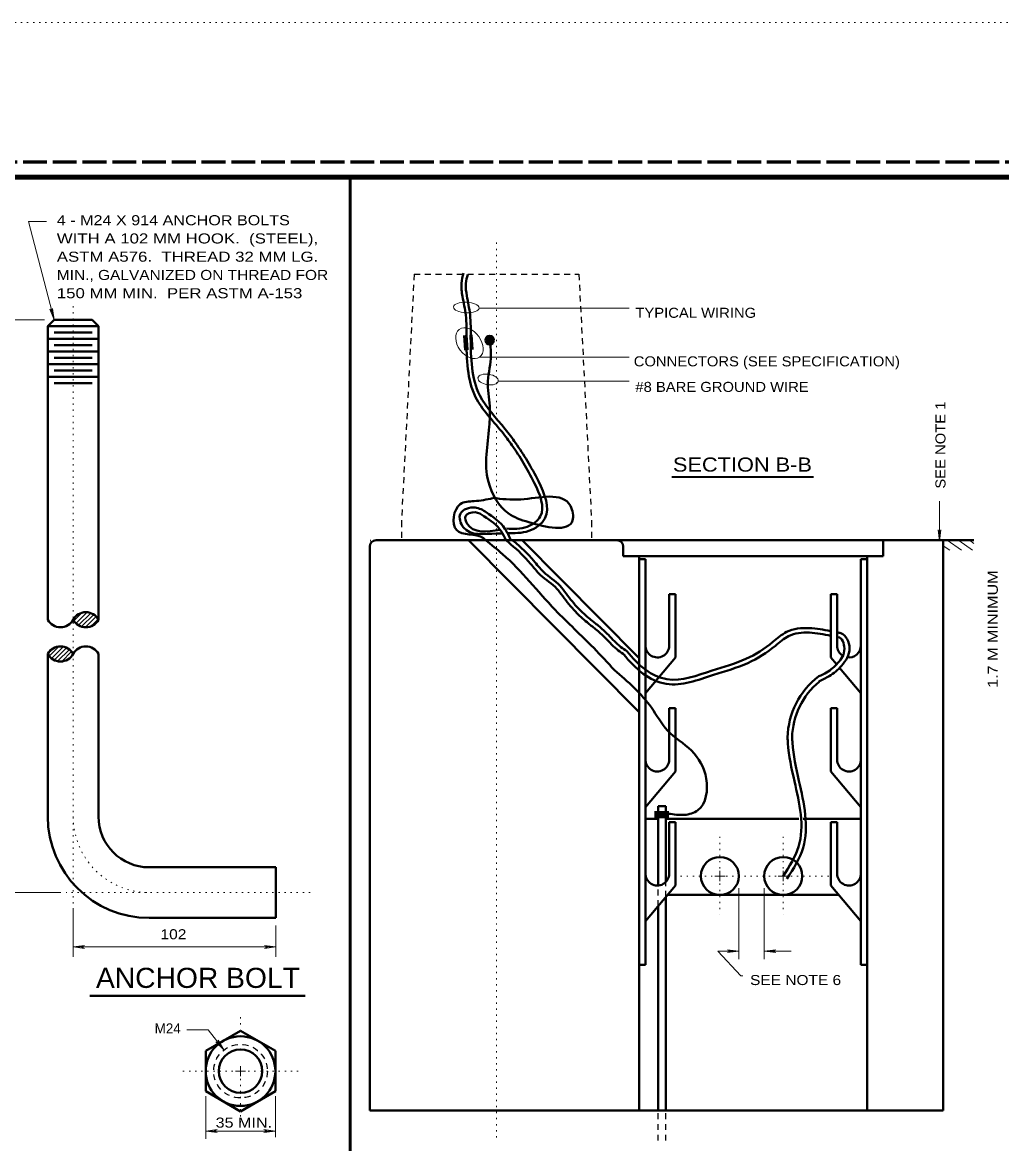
# Model space of a CAD drawing. Extents: x 312583 to 312854, y 144419 to 144597.
# Drawn here: x 312692.4 to 312766.4, y 144512 to 144596.8 of the extents above; entities that cross this region are included whole.
import ezdxf
from ezdxf.enums import TextEntityAlignment as Align

# ---------------------------------------------------------------- set-up
doc = ezdxf.new("R2010")
doc.units = 0
doc.header["$LTSCALE"] = 0.3
doc.header["$PDMODE"] = 32
doc.header["$PDSIZE"] = 0.15
for name, pattern in [('DOTTED', [1.5, 0.3, -1.2]), ('LONG_DASHED', [7.5, 6, -1.5]), ('SHORT_DASHED', [2.7, 1.5, -1.2])]:
    doc.linetypes.add(name, pattern=pattern)
doc.layers.add('1', color=7, linetype='Continuous', lineweight=13)
doc.layers.add('63', color=7, linetype='DOTTED', lineweight=13)

msp = doc.modelspace()

# ---------------------------------------------------------------- linework, layer by layer
at = {"layer": '1', "linetype": 'LONG_DASHED', "lineweight": 60}
msp.add_line((312851.75, 144586.2246), (312583.526, 144586.2246), dxfattribs=at)
at = {"layer": '1', "lineweight": 158}
msp.add_line((312616.5, 144585.0846), (312849, 144585.0846), dxfattribs=at)
at = {"layer": '1', "lineweight": 53}
msp.add_line((312717.1857, 144510.2401), (312717.1857, 144585.0846), dxfattribs=at)
at = {"layer": '1', "linetype": 'DOTTED'}
for p, q in [((312728.2437, 144580.1313), (312728.2437, 144557.6219)), ((312696.2334, 144529.6801), (312696.2334, 144575.4041)), ((312728.2437, 144557.6219), (312728.2437, 144512.2046)), ((312745.141, 144532.7973), (312745.141, 144535.2429)), ((312749.9327, 144532.7973), (312749.9327, 144535.2429)), ((312744.566, 144532.2223), (312741.7983, 144532.2223)), ((312745.141, 144531.6473), (312745.141, 144529.3243)), ((312749.3883, 144532.2223), (312745.5243, 144532.2223)), ((312749.9327, 144531.6473), (312749.9327, 144529.3243)), ((312750.5077, 144532.2223), (312753.6433, 144532.2223)), ((312714.1504, 144530.9681), (312695.6967, 144530.9681)), ((312708.8953, 144521.5448), (312708.8953, 144520.6072)), ((312708.3203, 144517.4639), (312704.487, 144517.4639)), ((312709.4703, 144517.4639), (312713.3036, 144517.4639)), ((312708.8953, 144516.8889), (312708.8953, 144513.5428))]:
    msp.add_line(p, q, dxfattribs=at)
at = {"layer": '1', "linetype": 'SHORT_DASHED', "lineweight": 25}
for p, q in [((312722.0183, 144577.7469), (312721.06, 144559.0556)), ((312722.0183, 144577.7469), (312734.4767, 144577.7469)), ((312734.4767, 144577.7469), (312735.435, 144559.0556)), ((312721.06, 144559.0556), (312721.06, 144557.6219)), ((312735.435, 144559.0556), (312735.435, 144557.6219)), ((312740.4643, 144529.9376), (312740.4643, 144531.5093)), ((312741.0623, 144530.6506), (312741.0623, 144531.7929)), ((312740.4643, 144512.2046), (312740.4643, 144514.4969)), ((312741.0623, 144512.2046), (312741.0623, 144514.4969))]:
    msp.add_line(p, q, dxfattribs=at)
at = {"layer": '1'}
for p, q in [((312694.4777, 144575.1051), (312694.6464, 144574.8598)), ((312694.7997, 144574.2925), (312694.4777, 144575.1051)), ((312694.6847, 144575.1588), (312694.6464, 144574.8598)), ((312694.7997, 144574.2925), (312694.6847, 144575.1588)), ((312694.079, 144574.2925), (312691.4785, 144574.2925)), ((312761.7463, 144557.546), (312761.7463, 144560.582)), ((312761.639, 144558.4124), (312761.7463, 144558.1364)), ((312761.7463, 144557.546), (312761.639, 144558.4124)), ((312761.8537, 144558.4124), (312761.7463, 144558.1364)), ((312761.7463, 144557.546), (312761.8537, 144558.4124)), ((312718.7217, 144557.6373), (312718.76, 144557.3459)), ((312762.5137, 144556.8553), (312762.0307, 144557.2003)), ((312763.3953, 144556.8553), (312762.322, 144557.6219)), ((312764.2387, 144556.8553), (312763.196, 144557.5989)), ((312764.3484, 144557.372), (312764.001, 144557.6219)), ((312696.2947, 144551.5148), (312696.9234, 144552.1435)), ((312696.448, 144551.3308), (312697.2914, 144552.1741)), ((312696.6397, 144551.1851), (312697.5674, 144552.1128)), ((312696.8774, 144551.0855), (312697.7897, 144551.9978)), ((312697.1764, 144551.0395), (312697.9814, 144551.8445)), ((312697.5904, 144551.1161), (312698.127, 144551.6528)), ((312694.424, 144548.8545), (312695.1524, 144549.5828)), ((312694.6004, 144548.6858), (312695.482, 144549.5675)), ((312694.8074, 144548.5555), (312695.7427, 144549.4831)), ((312695.0604, 144548.4711), (312695.9497, 144549.3528)), ((312695.3824, 144548.4558), (312696.1184, 144549.1918)), ((312745.141, 144532.2223), (312745.141, 144532.6056)), ((312749.9327, 144532.2223), (312749.9327, 144532.6056)), ((312745.141, 144532.2223), (312744.7577, 144532.2223)), ((312745.141, 144532.2223), (312745.141, 144531.8389)), ((312745.141, 144532.2223), (312745.5243, 144532.2223)), ((312749.9327, 144532.2223), (312749.5493, 144532.2223)), ((312749.9327, 144532.2223), (312749.9327, 144531.8389)), ((312749.9327, 144532.2223), (312750.316, 144532.2223)), ((312695.2904, 144530.9681), (312691.457, 144530.9681)), ((312746.5747, 144531.2946), (312746.5747, 144525.9356)), ((312748.4913, 144531.2946), (312748.4913, 144525.9356)), ((312696.2334, 144529.6801), (312696.2334, 144526.1151)), ((312711.5667, 144528.4688), (312711.5667, 144526.1151)), ((312696.2334, 144526.8588), (312697.0997, 144526.9661)), ((312696.2334, 144526.8588), (312711.5667, 144526.8588)), ((312696.2334, 144526.8588), (312697.0997, 144526.7515)), ((312697.0997, 144526.9661), (312696.8237, 144526.8588)), ((312697.0997, 144526.7515), (312696.8237, 144526.8588)), ((312710.7004, 144526.9661), (312710.9764, 144526.8588)), ((312711.5667, 144526.8588), (312710.7004, 144526.9661)), ((312710.7004, 144526.7515), (312710.9764, 144526.8588)), ((312711.5667, 144526.8588), (312710.7004, 144526.7515)), ((312744.9877, 144526.5413), (312746.5747, 144526.5413)), ((312745.7083, 144526.6486), (312745.9843, 144526.5413)), ((312746.5747, 144526.5413), (312745.7083, 144526.6486)), ((312745.7083, 144526.4339), (312745.9843, 144526.5413)), ((312746.5747, 144526.5413), (312745.7083, 144526.4339)), ((312748.4913, 144526.5413), (312749.3577, 144526.6486)), ((312748.4913, 144526.5413), (312750.523, 144526.5413)), ((312748.4913, 144526.5413), (312749.3577, 144526.4339)), ((312749.3577, 144526.6486), (312749.0817, 144526.5413)), ((312749.3577, 144526.4339), (312749.0817, 144526.5413)), ((312704.8396, 144520.5996), (312706.4343, 144520.5996)), ((312707.638, 144519.0662), (312706.4343, 144520.5996)), ((312707.0246, 144519.6796), (312707.2776, 144519.5262)), ((312707.638, 144519.0662), (312707.0246, 144519.6796)), ((312707.1933, 144519.8099), (312707.2776, 144519.5262)), ((312707.638, 144519.0662), (312707.1933, 144519.8099)), ((312708.8953, 144517.4639), (312708.8953, 144517.8472)), ((312708.8953, 144517.4639), (312708.512, 144517.4639)), ((312708.8953, 144517.4639), (312709.2786, 144517.4639)), ((312708.8953, 144517.4639), (312708.8953, 144517.0806)), ((312706.258, 144515.5626), (312706.258, 144512.3349)), ((312711.525, 144515.5626), (312711.525, 144512.4576)), ((312706.258, 144512.9329), (312707.1243, 144513.0402)), ((312706.258, 144512.9329), (312711.525, 144512.9329)), ((312706.258, 144512.9329), (312707.1243, 144512.8256)), ((312707.1243, 144513.0402), (312706.8483, 144512.9329)), ((312707.1243, 144512.8256), (312706.8483, 144512.9329)), ((312710.6586, 144513.0402), (312710.9346, 144512.9329)), ((312711.525, 144512.9329), (312710.6586, 144513.0402)), ((312710.6586, 144512.8256), (312710.9346, 144512.9329)), ((312711.525, 144512.9329), (312710.6586, 144512.8256))]:
    msp.add_line(p, q, dxfattribs=at)
at = {"layer": '1', "lineweight": 40}
for p, q in [((312694.3167, 144551.6068), (312694.3167, 144573.8095)), ((312697.6747, 144574.2925), (312694.7997, 144574.2925)), ((312697.6747, 144574.2925), (312698.15, 144573.8095)), ((312698.15, 144551.6068), (312698.15, 144573.8095)), ((312697.6747, 144573.3341), (312694.7997, 144573.3341)), ((312725.8133, 144573.1163), (312725.8823, 144572.0046)), ((312725.8747, 144573.1163), (312725.936, 144572.0123)), ((312725.913, 144573.1163), (312725.9743, 144572.0123)), ((312725.959, 144573.1239), (312726.0203, 144572.0123)), ((312725.9667, 144573.1239), (312726.028, 144572.0123)), ((312725.982, 144573.1239), (312726.0433, 144572.0123)), ((312726.2733, 144573.1393), (312726.3347, 144572.0353)), ((312726.3117, 144573.1393), (312726.373, 144572.0353)), ((312726.3423, 144573.1469), (312726.4037, 144572.0353)), ((312726.3653, 144573.1469), (312726.4267, 144572.0353)), ((312698.15, 144572.8511), (312694.3167, 144572.8511)), ((312697.6747, 144572.3758), (312694.7997, 144572.3758)), ((312698.15, 144571.8928), (312694.3167, 144571.8928)), ((312697.6747, 144571.4175), (312694.7997, 144571.4175)), ((312698.15, 144570.9345), (312694.3167, 144570.9345)), ((312697.6747, 144570.4591), (312694.7997, 144570.4591)), ((312698.15, 144569.9761), (312694.3167, 144569.9761)), ((312697.6747, 144569.5008), (312694.7997, 144569.5008)), ((312718.6603, 144557.1389), (312718.6603, 144514.4969)), ((312719.1433, 144557.6219), (312737.3517, 144557.6219)), ((312739.0307, 144544.6193), (312726.1277, 144557.6219)), ((312739.0307, 144548.6979), (312730.1757, 144557.6219)), ((312737.3517, 144557.6219), (312762.0307, 144557.6219)), ((312737.827, 144557.1389), (312737.827, 144556.4183)), ((312757.4767, 144557.6219), (312757.4767, 144556.4183)), ((312762.0307, 144557.6219), (312762.0307, 144555.7053)), ((312762.0307, 144557.6219), (312764.3484, 144557.6219)), ((312737.827, 144556.4183), (312757.4767, 144556.4183)), ((312739.0307, 144556.4183), (312739.0307, 144514.4969)), ((312739.0307, 144556.1806), (312739.506, 144556.1806)), ((312739.506, 144556.1806), (312739.506, 144525.5139)), ((312755.7977, 144556.1806), (312755.7977, 144525.5139)), ((312755.7977, 144556.1806), (312756.2807, 144556.1806)), ((312756.2807, 144556.4183), (312756.2807, 144514.4969)), ((312741.3077, 144553.5433), (312741.3077, 144549.6486)), ((312741.3077, 144553.5433), (312741.783, 144553.5433)), ((312741.783, 144553.5433), (312741.783, 144548.7516)), ((312753.5207, 144553.5433), (312753.5207, 144548.7516)), ((312754.0037, 144553.5433), (312753.5207, 144553.5433)), ((312754.0037, 144553.5433), (312754.0037, 144549.6486)), ((312694.3167, 144536.7181), (312694.3167, 144549.0155)), ((312698.15, 144536.7181), (312698.15, 144549.0155)), ((312739.506, 144546.0453), (312741.783, 144548.7516)), ((312753.95, 144548.2533), (312753.5207, 144548.7516)), ((312755.7977, 144546.0453), (312754.1723, 144547.9773)), ((312741.3077, 144544.9183), (312741.3077, 144541.0236)), ((312741.3077, 144544.9183), (312741.783, 144544.9183)), ((312741.783, 144544.9183), (312741.783, 144540.1266)), ((312753.5207, 144544.9183), (312753.5207, 144540.1266)), ((312754.0037, 144544.9183), (312753.5207, 144544.9183)), ((312754.0037, 144544.9183), (312754.0037, 144541.0236)), ((312739.506, 144537.4203), (312741.783, 144540.1266)), ((312755.7977, 144537.4203), (312753.5207, 144540.1266)), ((312740.4643, 144537.4969), (312741.0623, 144537.4969)), ((312740.4643, 144531.5093), (312740.4643, 144537.4969)), ((312741.0623, 144531.7929), (312741.0623, 144537.4969)), ((312739.506, 144536.5386), (312740.4643, 144536.5386)), ((312740.1883, 144537.0446), (312741.2693, 144537.0446)), ((312740.1883, 144536.9373), (312741.2693, 144536.9373)), ((312740.1883, 144536.8223), (312741.2693, 144536.8223)), ((312740.1883, 144536.6843), (312741.2693, 144536.6843)), ((312741.0623, 144536.5386), (312751.098, 144536.5386)), ((312751.443, 144536.5386), (312755.7977, 144536.5386)), ((312741.3077, 144536.2933), (312741.3077, 144532.3986)), ((312741.3077, 144536.2933), (312741.783, 144536.2933)), ((312741.783, 144536.2933), (312741.783, 144531.5016)), ((312753.5207, 144536.2933), (312753.5207, 144531.5016)), ((312754.0037, 144536.2933), (312753.5207, 144536.2933)), ((312754.0037, 144536.2933), (312754.0037, 144532.3986)), ((312711.5667, 144532.8848), (312701.9834, 144532.8848)), ((312711.5667, 144529.0515), (312711.5667, 144532.8848)), ((312739.506, 144528.7953), (312741.783, 144531.5016)), ((312755.7977, 144528.7953), (312753.5207, 144531.5016)), ((312741.0623, 144514.4969), (312741.0623, 144530.6506)), ((312741.1773, 144530.7886), (312754.1263, 144530.7886)), ((312740.4643, 144514.4969), (312740.4643, 144529.9376)), ((312711.5667, 144529.0515), (312701.9834, 144529.0515)), ((312739.0307, 144525.5139), (312739.506, 144525.5139)), ((312756.2807, 144525.5139), (312755.7977, 144525.5139)), ((312697.506, 144523.1481), (312713.7898, 144523.1481)), ((312706.258, 144518.9896), (312708.8876, 144520.5076)), ((312711.525, 144518.9896), (312708.8876, 144520.5076)), ((312706.258, 144515.9459), (312706.258, 144518.9896)), ((312711.525, 144515.9459), (312711.525, 144518.9896)), ((312708.8876, 144514.4202), (312706.258, 144515.9459)), ((312708.8876, 144514.4202), (312711.525, 144515.9459)), ((312718.6603, 144514.4969), (312762.0307, 144514.4969))]:
    msp.add_line(p, q, dxfattribs=at)
at = {"layer": '1', "lineweight": 35}
msp.add_line((312741.5048, 144562.4212), (312752.2152, 144562.4212), dxfattribs=at)
at = {"layer": '1'}
for points in [[(312694.217, 144581.7368), (312692.86, 144581.7368), (312694.7997, 144574.2925)], [(312726.925, 144575.1786), (312736.983, 144575.1786), (312738.2798, 144575.1786)], [(312726.971, 144571.4679), (312736.983, 144571.4679), (312738.2798, 144571.4679)], [(312728.3817, 144569.6586), (312736.983, 144569.6586), (312738.2798, 144569.6586)], [(312744.9877, 144526.5413), (312746.7127, 144524.6629), (312746.866, 144524.6629)]]:
    msp.add_lwpolyline(points, dxfattribs=at)
at = {"layer": '1', "lineweight": 40}
for points in [[(312698.15, 144573.8095), (312694.3167, 144573.8095), (312694.7997, 144574.2925)], [(312762.0307, 144555.7053), (312762.0307, 144554.5629), (312762.0307, 144514.4969)]]:
    msp.add_lwpolyline(points, dxfattribs=at)
for centre, radius in [((312727.729, 144572.7569), 0.3215), ((312727.729, 144572.7569), 0.2251), ((312727.729, 144572.7569), 0.1575), ((312727.729, 144572.7569), 0.1103), ((312745.1372, 144532.2223), 1.4375), ((312749.9288, 144532.2223), 1.4375), ((312708.8915, 144517.4639), 2.6335), ((312708.8915, 144517.4639), 1.6457)]:
    msp.add_circle(centre, radius, dxfattribs=at)
at = {"layer": '1', "linetype": 'SHORT_DASHED', "lineweight": 25}
msp.add_circle((312708.8915, 144517.4639), 2.0317, dxfattribs=at)
at = {"layer": '1', "lineweight": 40}
for centre, radius, start, end in [((312719.1424, 144557.1389), 0.4792, 90, 180), ((312737.3507, 144557.1389), 0.4792, 0, 90), ((312697.1917, 144551.0853), 1.0911, 28.55575, 151.44425), ((312695.275, 144552.1283), 1.0911, 208.55575, 331.44425), ((312697.1917, 144552.1283), 1.0911, 208.55575, 331.44425), ((312695.275, 144548.4939), 1.0911, 28.55575, 151.44425), ((312697.1917, 144548.4939), 1.0911, 28.55575, 151.44425), ((312740.4049, 144549.652), 0.8984, 178.12864, 359.96943), ((312754.9007, 144549.652), 0.8984, 180.03057, 236.00647), ((312754.9007, 144549.652), 0.8984, 259.65157, 1.86436), ((312695.275, 144549.537), 1.0911, 208.55575, 331.44425), ((312756.225, 144542.5718), 5.9687, 127.19211, 178.81798), ((312756.225, 144542.5718), 5.6257, 129.52896, 178.81421), ((312740.4049, 144541.027), 0.8984, 178.12864, 359.96943), ((312754.9007, 144541.027), 0.8984, 180.03057, 1.87136), ((312701.9834, 144536.7143), 7.6667, 180, 270), ((312701.9834, 144536.7143), 3.8333, 180, 270), ((312740.4049, 144532.402), 0.8984, 178.12864, 359.96943), ((312754.9007, 144532.402), 0.8984, 180.03057, 1.87136)]:
    msp.add_arc(centre, radius, start, end, dxfattribs=at)
at = {"layer": '1', "linetype": 'DOTTED'}
msp.add_arc((312701.9834, 144536.7143), 5.75, 180, 270, dxfattribs=at)
at = {"layer": '1'}
for centre, major_axis, ratio in [((312725.959, 144575.2217), (0.9679, -0.0403), 0.415149), ((312726.2005, 144572.5192), (0.7667, -1.0484), 0.671674), ((312727.6121, 144569.7774), (0.7667, -0.1217), 0.513795)]:
    msp.add_ellipse(centre, major_axis=major_axis, ratio=ratio, dxfattribs=at)
at = {"layer": '1', "lineweight": 40}
for points in [[(312725.9667, 144572.8786), (312725.9207, 144574.6496), (312725.6753, 144576.0526), (312725.5987, 144577.0569), (312725.7597, 144577.8236)], [(312726.2963, 144572.8863), (312726.2427, 144574.6803), (312726.005, 144576.0986), (312725.9283, 144577.0416), (312726.0663, 144577.7163)], [(312728.995, 144558.4959), (312730.5743, 144558.6416), (312731.548, 144559.4083), (312731.1033, 144561.9613), (312729.4167, 144564.7979), (312728.6423, 144565.8329), (312726.6643, 144568.4473), (312725.9667, 144572.8786)], [(312729.018, 144558.1663), (312730.697, 144558.3273), (312731.9083, 144559.2703), (312731.4177, 144562.0763), (312729.685, 144564.9819), (312728.903, 144566.0323), (312726.9787, 144568.5776), (312726.2887, 144572.9246)], [(312727.96, 144560.8189), (312730.0837, 144560.7116), (312733.8327, 144560.2209), (312734.0013, 144559.1093), (312730.697, 144558.9789), (312729.133, 144559.6613), (312727.6303, 144562.0456), (312727.6993, 144566.1933), (312727.73, 144567.7649), (312727.5997, 144569.6586), (312727.8297, 144571.6136), (312727.73, 144572.7559)], [(312727.4157, 144557.6219), (312727.2623, 144557.7676), (312725.2153, 144558.3963), (312725.5067, 144560.3513), (312726.5493, 144560.5736), (312727.9523, 144560.7883)], [(312729.3247, 144557.6219), (312728.88, 144558.4883), (312727.477, 144559.7303), (312726.626, 144560.0906), (312725.5143, 144559.6306), (312725.7443, 144558.5879), (312728.2207, 144558.1279), (312728.7113, 144558.1279)], [(312728.949, 144557.6219), (312728.6117, 144558.2813), (312727.293, 144559.4466), (312726.626, 144559.7303), (312725.8977, 144559.4313), (312726.0203, 144558.8716), (312728.512, 144558.4116)], [(312737.1677, 144547.7933), (312735.596, 144549.4723), (312732.6903, 144552.3473), (312728.7113, 144556.5639), (312727.4157, 144557.6219)], [(312737.9497, 144548.9356), (312737.4437, 144549.2883), (312736.4853, 144550.2159), (312735.7417, 144550.8906), (312735.09, 144551.4119), (312734.216, 144552.2169), (312733.25, 144553.3823), (312732.813, 144553.9496), (312731.5787, 144554.9846), (312730.8197, 144555.8433), (312729.34, 144557.2999), (312728.949, 144557.6219)], [(312738.1107, 144549.2269), (312737.6583, 144549.5413), (312736.7077, 144550.4536), (312735.9563, 144551.1436), (312735.3047, 144551.6649), (312734.4537, 144552.4469), (312733.5107, 144553.5893), (312733.0507, 144554.1796), (312731.8087, 144555.2223), (312731.0573, 144556.0733), (312729.5547, 144557.5453), (312729.4627, 144557.6219)], [(312753.5053, 144550.7449), (312751.8953, 144550.9749), (312750.1857, 144550.6836), (312749.143, 144549.9246), (312747.1113, 144548.6443), (312744.5583, 144547.7626), (312741.1313, 144547.1109), (312739.529, 144547.8086), (312738.1107, 144549.2269)], [(312753.5283, 144550.3923), (312751.903, 144550.6299), (312750.3237, 144550.3616), (312749.3347, 144549.6409), (312747.257, 144548.3299), (312744.6503, 144547.4329), (312741.0853, 144546.7583), (312739.3297, 144547.5249), (312737.8423, 144549.0046)], [(312752.616, 144546.9423), (312753.398, 144547.3333), (312754.341, 144548.1306), (312754.939, 144549.4416), (312754.2797, 144550.5916), (312754.0037, 144550.6376)], [(312752.616, 144547.3256), (312753.2063, 144547.6246), (312754.065, 144548.3453), (312754.5557, 144549.4263), (312754.065, 144550.2773), (312754.0037, 144550.2773)], [(312741.2693, 144536.9373), (312742.4423, 144536.8453), (312743.4773, 144537.2056), (312744.106, 144539.5899), (312742.979, 144541.7059), (312741.1773, 144543.2393), (312739.9583, 144544.9566), (312737.1677, 144547.7933)], [(312749.9327, 144532.2223), (312751.0903, 144534.4379), (312750.776, 144539.3906), (312750.2777, 144542.2733), (312750.2547, 144542.6949)], [(312750.201, 144532.0076), (312751.4353, 144534.3613), (312751.1133, 144539.4289), (312750.6227, 144542.3116), (312750.5997, 144542.6949)]]:
    msp.add_spline(points, degree=3, dxfattribs=at)
at = {"layer": '1'}
msp.add_point((312694.5007, 144549.2685), dxfattribs=at)
at = {"layer": '63'}
msp.add_line((312601.2, 144596.7846), (312853.5, 144596.7846), dxfattribs=at)

# ---------------------------------------------------------------- texts
at = {"layer": '1'}
for s, width, p in [('4 - M24 X 914 ANCHOR BOLTS', 1.2, (312694.999, 144581.4445)), ('WITH A 102 MM HOOK.  (STEEL), ', 1.25, (312694.999, 144580.0645)), ('ASTM A576.  THREAD 32 MM LG.', 1.25, (312694.999, 144578.6845)), ('MIN., GALVANIZED ON THREAD FOR', 1.15, (312694.999, 144577.3045)), ('150 MM MIN.  PER ASTM A-153', 1.25, (312694.999, 144575.9245)), ('TYPICAL WIRING', 1.1, (312738.7475, 144574.4416)), ('CONNECTORS (SEE SPECIFICATION)', 1.1, (312738.6248, 144570.7693)), ('#8 BARE GROUND WIRE', 1.1, (312738.7475, 144568.8373)), ('102 ', 1.15, (312702.844, 144527.4382)), ('SEE NOTE 6', 1.15, (312747.4196, 144523.9743)), ('35 MIN. ', 1.2, (312707.0066, 144513.192))]:
    msp.add_text(s, height=0.76, dxfattribs=dict(at, width=width)).set_placement(p)
for s, width, p in [('SEE NOTE 1', 1.1, (312762.1968, 144561.5217)), ('1.7 M MINIMUM', 1.2, (312766.1519, 144546.4594))]:
    msp.add_text(s, height=0.76, rotation=90, dxfattribs=dict(at, width=width)).set_placement(p)
for s, height, width, p in [('SECTION B-B', 1.07, 1.15, (312746.8426, 144562.8075)), ('ANCHOR BOLT', 1.52, 1.05, (312705.6673, 144523.7584))]:
    msp.add_text(s, height=height, dxfattribs=dict(at, width=width)).set_placement(p, align=Align.CENTER)
msp.add_text('M24', height=0.76, dxfattribs=at).set_placement((312702.3954, 144520.3107))

doc.saveas('drawing.dxf')
